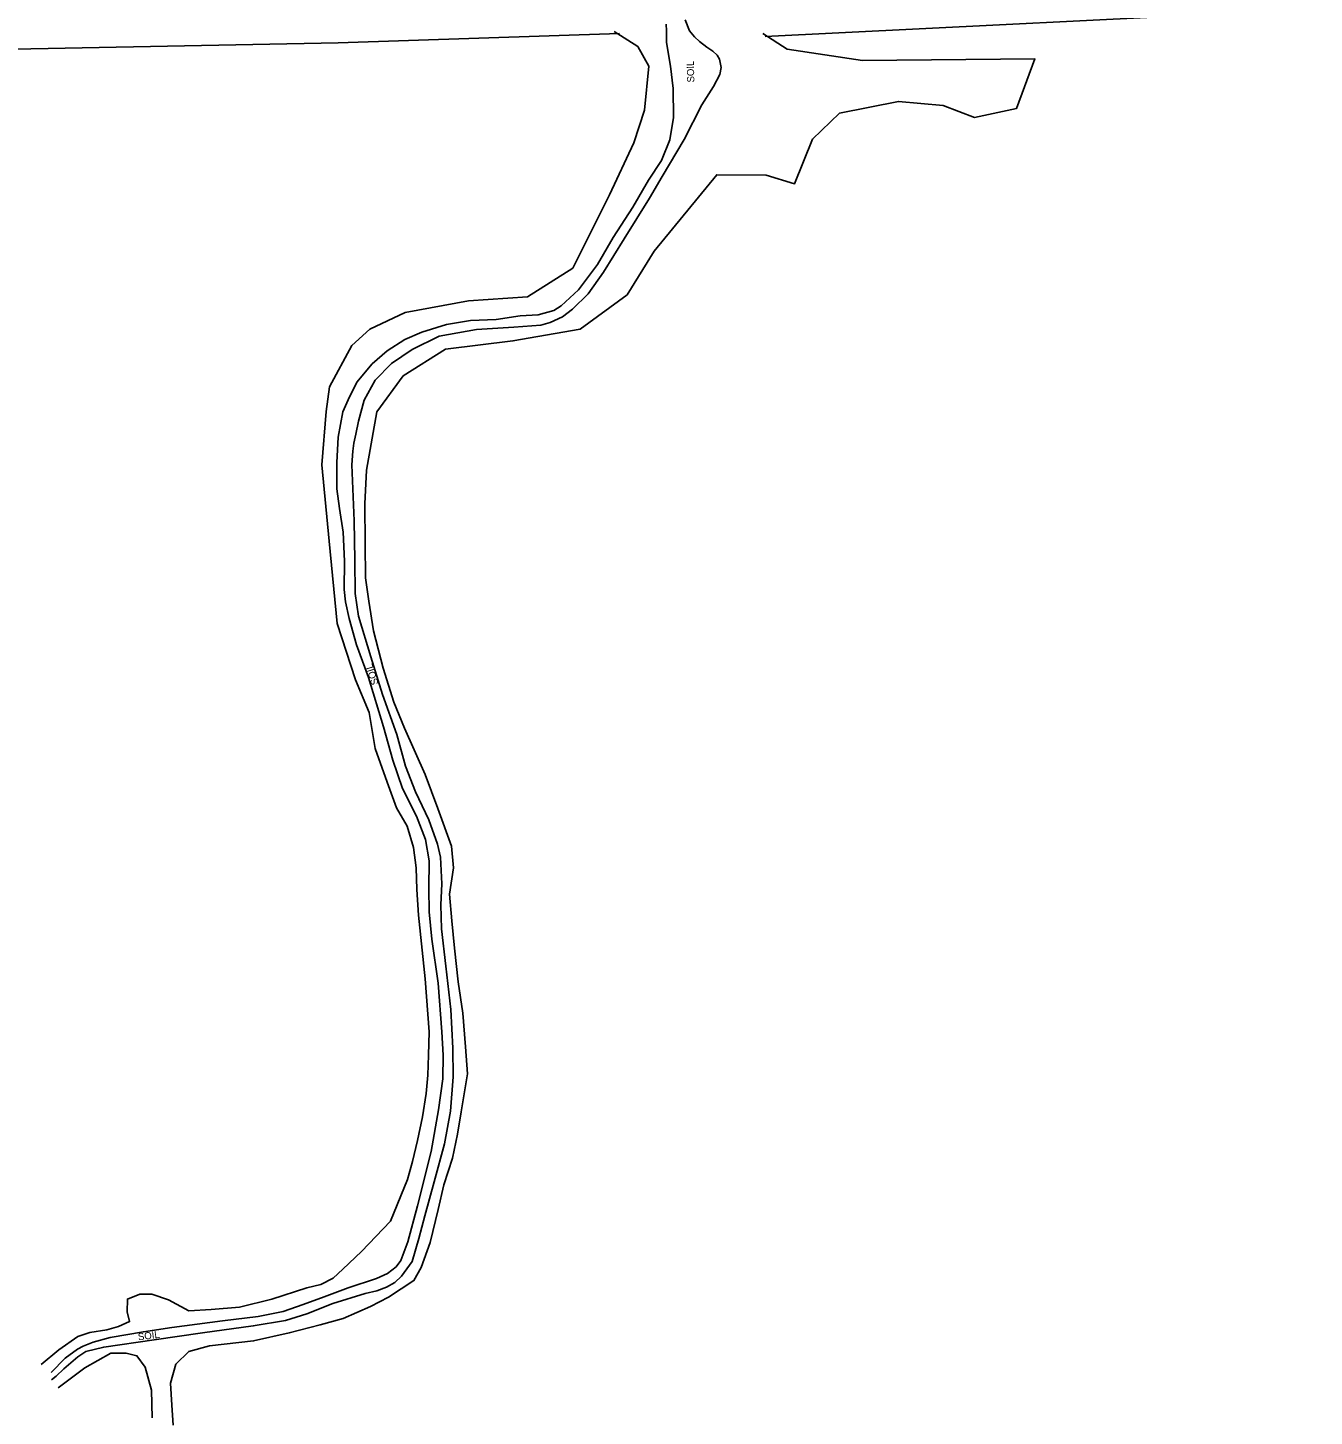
# Model space of a CAD drawing. Extents: x 2030130 to 2036320, y 723205 to 762423.
# Drawn here: x 2031448 to 2032167, y 753557 to 754334 of the extents above; entities that cross this region are included whole.
import ezdxf

# ---------------------------------------------------------------- set-up
doc = ezdxf.new("R2010")
doc.units = 0
for name, color, linetype in [('Draft_Station Labels Major', 7, 'Continuous'), ('Draft_Station Tics Major', 7, 'Continuous'), ('Old_Level_23', 7, 'Continuous')]:
    doc.layers.add(name, color=color, linetype=linetype)

msp = doc.modelspace()

# ---------------------------------------------------------------- linework, layer by layer
at = {"layer": 'Draft_Station Labels Major'}
for points in [[(2031620.45, 754090.28), (2031621.35, 754104.43), (2031623.97, 754118.6), (2031626.94, 754125.47), (2031631.69, 754135.2), (2031640.32, 754145.63), (2031648.7, 754152.74), (2031658.51, 754159.19), (2031668.06, 754163.27), (2031681.78, 754167.59), (2031695.33, 754169.71), (2031709.66, 754170.42), (2031723.13, 754172.36), (2031733.18, 754173.02), (2031741.89, 754175.29), (2031746.05, 754177.99), (2031755.74, 754187.01), (2031766.23, 754201.07), (2031775.1, 754216.16), (2031786.14, 754233.16), (2031794.82, 754248.34), (2031802.02, 754259.23), (2031806.85, 754270.86), (2031808.81, 754283.32), (2031808.65, 754299.55), (2031807.11, 754312.07), (2031804.98, 754325.34), (2031804.83, 754331.89), (2031804.79, 754335.59)], [(2031815.3, 754337.97), (2031817.74, 754331.92), (2031820.52, 754328.53), (2031823.4, 754325.9), (2031827.51, 754322.71), (2031830.76, 754320.46), (2031833.25, 754318.21), (2031834.51, 754315.94), (2031835.41, 754311.4), (2031834.69, 754307.4), (2031831.24, 754300.72), (2031824.6, 754290.5), (2031814.72, 754271.04), (2031802.4, 754250.31), (2031795.39, 754238.28), (2031781.19, 754215.45), (2031769.69, 754196.74), (2031761.17, 754184.79), (2031752.33, 754176.06), (2031746.67, 754171.83), (2031739.78, 754168.63), (2031734.66, 754167.25), (2031719.58, 754166.06), (2031698.71, 754164.81), (2031677.76, 754161.09), (2031662.74, 754153.63), (2031651.04, 754145.73), (2031642.02, 754136.44), (2031635.87, 754125.18), (2031632.66, 754113.47), (2031631.11, 754106.24), (2031630.12, 754101.2), (2031629.4, 754096.63), (2031628.91, 754089.03)], [(2031460.74, 753581.23), (2031468.7, 753589.3), (2031475.45, 753594.39), (2031478.59, 753595.96), (2031484.32, 753598.15), (2031493.7, 753600.77), (2031512.37, 753604.09), (2031528.27, 753606.41), (2031556.64, 753610.24), (2031576.47, 753612.62), (2031590.55, 753615.3), (2031601.73, 753619.29), (2031613.47, 753623.67), (2031626.85, 753628.55), (2031642.81, 753633.94), (2031648.91, 753636.71), (2031653.67, 753640.32), (2031656.31, 753643.91), (2031660.2, 753654.33), (2031665.59, 753674.56), (2031673.35, 753704.99), (2031677.46, 753728.18), (2031679.73, 753745.49), (2031679.93, 753758.74), (2031679.18, 753771.88), (2031677.29, 753799.02), (2031673.6, 753823.73), (2031672.15, 753838.98), (2031672.08, 753851.94), (2031672.16, 753867.58), (2031670.08, 753879.36), (2031665.01, 753892.45), (2031657.22, 753907.89), (2031651.83, 753923.85), (2031646.59, 753942.4), (2031638.26, 753970.13), (2031631.49, 753988.37), (2031627.36, 754003.1), (2031625.41, 754012.39), (2031624.55, 754019.29), (2031624.82, 754035.13), (2031624.13, 754051.34), (2031622.03, 754064.66), (2031620.54, 754075.58), (2031620.45, 754090.28)], [(2031628.91, 754089.03), (2031630.28, 754057.66), (2031630.57, 754035.78), (2031630.73, 754017.06), (2031632.62, 754004.32), (2031639.64, 753981.57), (2031646.16, 753960.64), (2031654.04, 753938.09), (2031658.98, 753920.39), (2031664.54, 753906.17), (2031672.05, 753890.52), (2031676.93, 753876.76), (2031678.56, 753869.59), (2031679.34, 753854.62), (2031678.63, 753842.81), (2031679.09, 753829.38), (2031681.58, 753808.67), (2031684.3, 753784.43), (2031685.35, 753762.75), (2031685.56, 753746.72), (2031684.09, 753727.41), (2031680.78, 753709.12), (2031674.92, 753687.93), (2031669.8, 753668.95), (2031666.41, 753656.14), (2031662.74, 753643.42), (2031656.71, 753635.18), (2031652.92, 753631.68), (2031648.34, 753629.02), (2031642.99, 753627.03), (2031636.3, 753625.41), (2031618.23, 753619.89), (2031603.72, 753614.03), (2031591.86, 753610.33), (2031573.76, 753607.3), (2031545.4, 753603.47), (2031518.38, 753599.47), (2031490.22, 753595.44), (2031480.26, 753593.1), (2031475.7, 753590.07), (2031471.81, 753586.66), (2031467.92, 753583.25), (2031463.55, 753579.25), (2031460.89, 753577.11)]]:
    msp.add_lwpolyline(points, dxfattribs=at)
at = {"layer": 'Draft_Station Tics Major'}
for p, q in [((2031860.04, 754328.57), (2032167.14, 754343.97)), ((2031621.34, 754325.16), (2031778.7, 754330.25)), ((2031429.42, 754321.34), (2031621.33, 754325.16))]:
    msp.add_line(p, q, dxfattribs=at)
for points in [[(2031775.65, 754331.53), (2031788.87, 754323.13), (2031795.08, 754312.14), (2031792.65, 754287.54), (2031786.73, 754269.19), (2031773.1, 754240.09), (2031752.54, 754199.11), (2031727.17, 754183.05), (2031694.22, 754180.82), (2031658.84, 754174.19), (2031638.93, 754164.85), (2031628.92, 754155.79), (2031616.38, 754132.61), (2031614.61, 754118.88), (2031612.23, 754089.13)], [(2031637.04, 754086.01), (2031642.82, 754118.65), (2031657.67, 754138.76), (2031681.34, 754153.83), (2031719.02, 754158.39), (2031756.69, 754164.85), (2031782.99, 754184.17), (2031797.99, 754208.51), (2031833.02, 754251.35), (2031860.65, 754251.05), (2031876.51, 754246.25), (2031886.56, 754271.31), (2031901.66, 754285.74), (2031934.56, 754292.35), (2031959.55, 754290.12), (2031977.14, 754283.43), (2032000.72, 754288.43), (2032010.93, 754316.16), (2031914.52, 754315.22), (2031872.35, 754321.66), (2031858.7, 754330.25)], [(2031612.23, 754089.13), (2031616.19, 754046.28), (2031620.64, 754000.36), (2031630.91, 753968.81), (2031638.64, 753950.48), (2031642.06, 753930.44), (2031648.65, 753911.52), (2031653.94, 753897.08), (2031659.93, 753886.84), (2031663.44, 753874.98), (2031664.84, 753863.67), (2031665.2, 753851.39), (2031666.25, 753837.1), (2031669.98, 753801.45), (2031672.1, 753771.81), (2031671.89, 753758.76), (2031671.37, 753747.52), (2031670.45, 753737.43), (2031668.51, 753724.25), (2031665.71, 753711.06), (2031662.89, 753699.22), (2031660.05, 753689.3), (2031650.57, 753665.94), (2031634.28, 753649.02), (2031623.85, 753639), (2031618.54, 753634.03), (2031611.58, 753630.48), (2031603.83, 753628.56), (2031584.14, 753622.25), (2031566.06, 753617.79), (2031550.34, 753616.52), (2031537.68, 753615.68), (2031526.46, 753621.87), (2031517.11, 753625.01), (2031510.39, 753625.02), (2031503.42, 753622.33), (2031503.22, 753615.13), (2031504.64, 753609.77), (2031498.44, 753606.91), (2031491.93, 753605.09), (2031482.35, 753603.62), (2031475.76, 753601.42), (2031465.01, 753593.89), (2031455.23, 753585.79)], [(2031528.92, 753551.73), (2031528.2, 753563.05), (2031527.46, 753575.23), (2031530.49, 753586.02), (2031537.69, 753593.03), (2031549.36, 753596.26), (2031573.99, 753598.98), (2031593.9, 753603.37), (2031611.21, 753607.92), (2031624.12, 753611.55), (2031639.39, 753618.28), (2031649.5, 753623.4), (2031663.68, 753632.71), (2031667.71, 753640.06), (2031672.8, 753654.04), (2031677.16, 753672.44), (2031680.44, 753686.21), (2031685.23, 753701.15), (2031687.93, 753714.62), (2031690.15, 753727), (2031693.58, 753748.33), (2031692.44, 753763.51), (2031690.99, 753782.32), (2031688.34, 753799.86), (2031686.36, 753818.56), (2031684.82, 753833.89), (2031683.56, 753848.95), (2031685.84, 753863.54), (2031684.72, 753875.62), (2031676.98, 753896.85), (2031669.91, 753915.86), (2031658.34, 753941.72), (2031652.48, 753956.33), (2031646.47, 753975.35), (2031641.1, 753996.21), (2031638.49, 754012.68), (2031636.49, 754025.9), (2031636.43, 754044.81), (2031636.13, 754067.27), (2031637.04, 754086.01)], [(2031464.77, 753572.74), (2031479.6, 753583.88), (2031494.22, 753592.07), (2031502.67, 753591.99), (2031508.73, 753590.63), (2031513.42, 753584.26), (2031516.95, 753571.35), (2031517.35, 753555.9)]]:
    msp.add_lwpolyline(points, dxfattribs=at)

# ---------------------------------------------------------------- texts
at = {"layer": 'Old_Level_23'}
for rotation, p in [(91.50831, (2031820.49, 754303)), (107.5411, (2031643.91, 753966.61)), (6.99703, (2031509.56, 753599.2))]:
    msp.add_text('SOIL', height=4, rotation=rotation, dxfattribs=at).set_placement(p)

doc.saveas('drawing.dxf')
